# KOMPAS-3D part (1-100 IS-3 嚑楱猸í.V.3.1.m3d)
File: created 28.02.2017 17:17:02, last saved 28.02.2017 17:17:02.
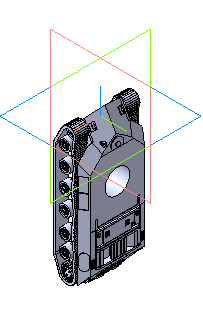
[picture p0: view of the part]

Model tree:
1. Операция без истории:1
2. Операция без истории:2
3. Операция без истории:3
4. Операция без истории:4
5. Операция без истории:5
6. Операция без истории:6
